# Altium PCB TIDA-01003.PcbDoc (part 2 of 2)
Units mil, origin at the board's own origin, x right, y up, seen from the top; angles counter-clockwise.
Board outline 1055.12 x 1877.5 mil, 6 copper layers (Layer 1 - Top Layer, Layer 2 - GND, Layer 3 - Signal, Layer 4 - Power, Layer 5 - GND, Layer 6 - Bottom Layer), stack 66.271 mil thick; 84 components, 50 nets, 343 pads, 124 vias.
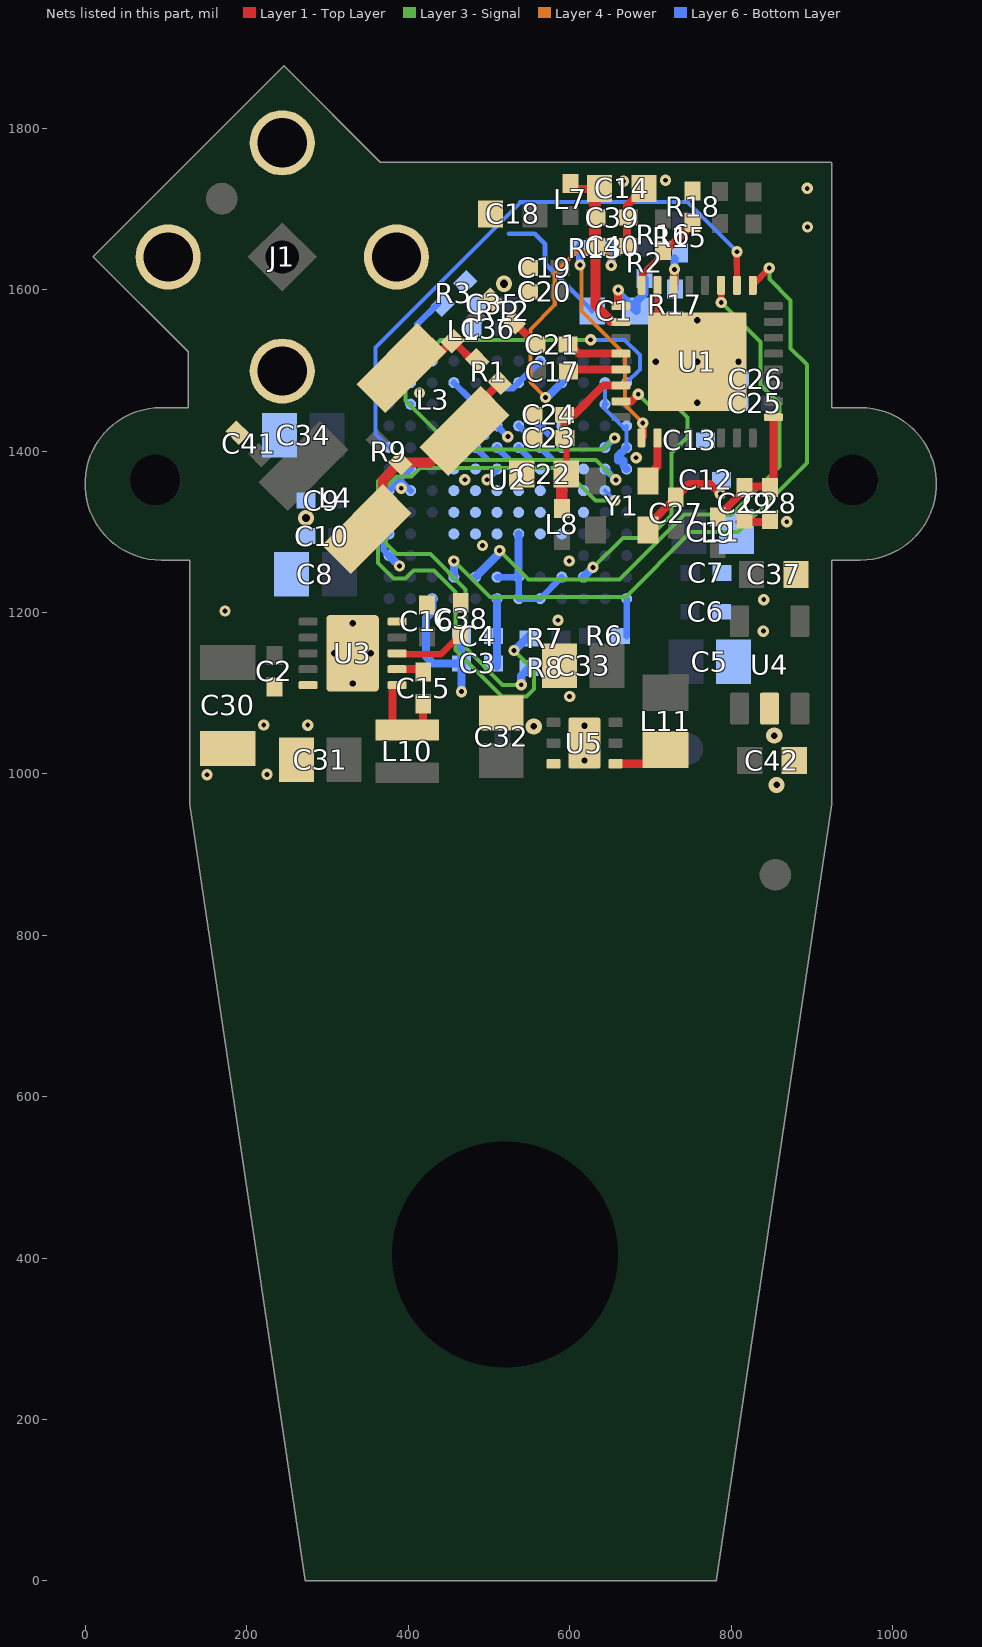
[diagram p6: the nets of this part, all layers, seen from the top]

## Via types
v1: diameter 14, hole 6, Layer 1 - Top Layer to Layer 6 - Bottom Layer, tented both sides, 103 vias
v2: diameter 19.68, hole 7.87, Layer 1 - Top Layer to Layer 6 - Bottom Layer, 10 vias
v3: diameter 20, hole 8, Layer 1 - Top Layer to Layer 6 - Bottom Layer, tented both sides, 6 vias
v4: diameter 20, hole 10, Layer 1 - Top Layer to Layer 6 - Bottom Layer, tented both sides, 4 vias
v5: diameter 19.68, hole 7.87, Layer 1 - Top Layer to Layer 6 - Bottom Layer, tented bottom, 1 vias

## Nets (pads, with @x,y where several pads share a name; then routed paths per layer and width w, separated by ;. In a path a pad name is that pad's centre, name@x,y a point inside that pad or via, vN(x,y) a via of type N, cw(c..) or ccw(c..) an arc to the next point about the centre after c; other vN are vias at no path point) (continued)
GND: C1.2 C2.2 C3.2 C4.2 C5.2 C6.2 C7.2 C8.2 C9.2 C10.2 C11.2 C12.2 C13.2 C14.2 C16.2 C18.2 C19.2 C20.2 C22.2 C23.2 C24.2 C25.2 C26.2 C27.2 C28.2 C29.2 C30.2 C31.2 C32.2 C33.2 C34.2 C35.2 C36.2 C37.2 C38.2 C39.2 C40.2 C41.2 C42.2 J1.2 J1.3 J1.4 J1.5 R3.1 R12.2 R17.1 R18.1 U1.7 U1.33 U2.A3 U2.A7 U2.A8 U2.B6 U2.B7 U2.B9 U2.C1 U2.D1 U2.D4 U2.D5 U2.D6 U2.D7 U2.D8 U2.D9 U2.E4 U2.E5 U2.E6 U2.E7 U2.E8 U2.E9 U2.E10 U2.F1 U2.F2 U2.F4 U2.F5 U2.F6 U2.F7 U2.F8 U2.F9 U2.F10 U2.G2 U2.G4 U2.G5 U2.G6 U2.G7 U2.G8 U2.G9 U2.G10 U2.G12 U2.H4 U2.H5 U2.H6 U2.H7 U2.H8 U2.H9 U2.H12 U2.J4 U2.J5 U2.J6 U2.J7 U2.J8 U2.J9 U2.J12 U2.K2 U2.K11 U2.L2 U2.L4 U2.L6 U2.L7 U2.L11 U2.M8 U3.5 U3.10 U3.11@331,1149.5 U4.2 U5.6 U5.7@618.3,1038.3 Y1.2 | length 1460.2
  Layer 1 - Top Layer w8: U1.33@708.95,1560.22 U1.7@708.95,1605.5
  Layer 1 - Top Layer w10: C40.2@671.1,1655.09 671.1,1704.54 C14.2@692.06,1725.5 ; Y1.2@696.98,1307.99 732.68,1343.69 C27.2@733,1343.69 ; C27.2@733,1344.54 747.86,1359.4 774,1359.5 v1(786.5,1347) ; C29.2@810.7,1312.41 C28.2@847.6,1312.41
  Layer 6 - Bottom Layer w5: U2.K11@641.2,1454.8 U2.J12@667.5,1428.5 ; U2.K11@643.6,1461.5 U2.L11@643.63,1479.17 ; U2.H12@670.65,1404.59 U2.J12@670.65,1431.36
  Layer 6 - Bottom Layer w6: 525,1669.5 556.7,1669.3 569.5,1656.5 569.5,1632 C1.2@627.84,1573.9
  Layer 6 - Bottom Layer w8: U2.C1@376.16,1270.73 369.47,1277.42 369.47,1290.81 U2.D1@376.16,1297.5 ; U2.F1@376.16,1351.04 389.54,1364.43 ; U2.F2@402.93,1351.04 389.54,1364.43 ; U2.G2@402.93,1377.82 389.54,1364.43 ; U2.L2@402.93,1484.9 U2.L2@402.93,1484.96 ; U2.H4@456.47,1404.59 469.86,1391.2 ; U2.J4@456.47,1431.36 469.86,1417.97 ; U2.L4@456.47,1484.9 477.36,1464.02 U2.J5@477.36,1432.97 ; U2.H5@483.25,1404.59 496.63,1391.2 ; U2.J5@483.25,1431.36 496.63,1417.97 ; v1@497,1364 U2.G6@509.79,1376.75 ; U2.B6@510.02,1243.96 U2.B7@536.79,1243.96 U2.A7@536.79,1217.19 U2.A8@563.56,1217.19 U2.B9@590.33,1243.96 ; U2.H6@510.02,1404.59 523.4,1391.2 ; U2.J6@510.02,1431.36 v1(523.4,1417.97) ; U2.L6@510.02,1484.9 516.95,1477.97 529.86,1477.97 550.17,1498.29 ; U2.H7@536.79,1404.59 550.17,1391.2 ; U2.J7@536.79,1431.36 550.17,1417.97 ; 550.17,1498.29 U2.M8@563.56,1511.67 ; U2.H8@563.56,1404.59 576.95,1391.2 ; U2.J8@563.56,1431.36 576.95,1417.97
  Layer 6 - Bottom Layer w10: U2.C1@376.16,1270.73 v1(389.1,1257.8) ; U2.A3@429.7,1217.19 429.7,1200.74 422,1193.04 422,1145.5 430.6,1136.9 C3.2@466.11,1136.9 ; v1(466,1102) 466.11,1122.39 C3.2@466.11,1136.9 ; C4.2@466.11,1170.7 C3.2@466.11,1136.9 ; U2.B7@536.79,1243.96 U2.D7@536.79,1297.5 ; 660.1,1388.36 660.1,1394.04 U2.H12@670.65,1404.59 ; 666.5,1388.36 666.5,1381.96 U2.G12@670.65,1377.82 ; R17.1@730.97,1562.18 v5(758,1562.18) v5@757.33,1561.51 ; C25.2@809.81,1459.45 v2@809.81,1510.37
  Layer 6 - Bottom Layer w15: J1.2@363.97,1627.31 J1.2@381.3,1644.63
  other v1: 150.5,999 225,999.5 275.5,1060.5 221,1060.8 600,1096 840,1177 585.5,1190.5 173,1202 840.5,1216 599.4,1264 492,1283.2 869,1312.5 391.3,1354 470.1,1364.5 497.5,1364.5 682.4,1391.8 414,1472 894.7,1677.9 894.4,1725.7 666.8,1734.5 718.7,1735.8
  other v2: 618.3,1016.65 618.3,1059.95 331,1112.1 308.36,1149.5 353.64,1149.5 331,1186.9 758,1459.82 706.82,1511 758,1511 809.18,1511
  other v3: 856.5,986.5 853.5,1047.5 555.5,1059
  other v4: 273.5,1317 518.5,1607.5
HSYNC: U1.1 U2.B4 | length 834.4
  Layer 1 - Top Layer w8: U1.1@827.06,1605.5 828.16,1606.6 v1(847.4,1627)
  Layer 3 - Signal w5: v1(456.5,1263.8) 501,1219.5 669.5,1219.5 750,1300 808,1300 ; 808.5,1300 894,1385.5 894,1507.1 873.7,1527.4 873.7,1586.8 847.4,1613.1 v1(847.4,1627) v1@847.4,1626.9
  Layer 6 - Bottom Layer w10: U2.B4@456.47,1243.96 v1(456.5,1263.8)
NetC1_1: C1.1 R2.1 U1.9 | length 95.5
  Layer 1 - Top Layer w10: U1.9@660.2,1583.21 v1(660.2,1599.6)
  Layer 6 - Bottom Layer w10: v1(660.2,1599.6) 660.2,1596.66 C1.1@682.96,1573.9 682.96,1585.26 692.8,1595.1 R2.1@692.8,1613.82
NetC3_1: C3.1 C4.1 U2.A6 | length 84.6
  Layer 6 - Bottom Layer w10: U2.A6@508.6,1217.19 U2.A6@508.6,1218.13 ; C3.1@510,1133.5 U2.A6@510.02,1217.19
NetC14_1: C14.1 C39.1 C40.1 L7.2 U1.10 | length 209.4
  Layer 1 - Top Layer w10: L7.2@597.19,1725 C14.1@636.44,1725
  Layer 1 - Top Layer w12: 631.9,1580.3 651.2,1561 ; 631.9,1582.5 C40.1@631.9,1650.9
  Layer 1 - Top Layer w15: C40.1@631.29,1652.41 631.6,1673.41 C14.1@631.4,1726.9
NetC15_1: C15.1 U3.2 | length 28.4
  Layer 1 - Top Layer w10: U3.2@382.62,1129.81 C15.1@411,1130
NetC15_2: C15.2 L10.1 U3.1 | length 90.4
  Layer 1 - Top Layer w10: L10.1@380.5,1054.5 U3.1@380.62,1110.13 ; L10.1@418.5,1049.5 C15.2@418.5,1084.31
NetC17_2: C17.2 U1.13 | length 62.7
  Layer 1 - Top Layer w10: C17.2@601,1501.17 U1.13@663.67,1501.17
NetC21_1: C21.1 R12.1 | length 22.9
  Layer 1 - Top Layer w10: R12.1@537.19,1553.5 C21.1@553.5,1537.5
NetC21_2: C21.2 U1.12 | length 71.4
  Layer 1 - Top Layer w10: C21.2@597.69,1534 610.83,1520.85 U1.12@663.67,1520.85
NetC22_1: C22.1 C23.1 C24.1 L8.2 U1.14 | length 194
  Layer 1 - Top Layer w8: C22.1@596.06,1374.5 C23.1@596.06,1409.41
  Layer 1 - Top Layer w10: C23.1@593.68,1417.2 C24.1@593.68,1445 605.31,1445.01 641.7,1481.4 U1.14@663.67,1481.49
  Layer 1 - Top Layer w14: L8.2@590.2,1327.39 C22.1@590.2,1373.64
NetC28_1: C28.1 C29.1 L9.2 U1.25 | length 163.5
  Layer 1 - Top Layer w10: L9.2@783.5,1318.69 C29.1@812,1347.19 ; C29.1@812,1356 816.48,1356.02 846.8,1356.18 852.65,1362.03 U1.25@852.65,1442.11
NetC38_1: C38.1 U3.3 | length 88.5
  Layer 1 - Top Layer w8: U3.3@386.5,1148.5 440.5,1148.5 C38.1@465,1172.82
NetL1_2: L1.2 L3.1 R1.2 | length 70.8
  Layer 1 - Top Layer w10: L3.1@430.5,1513 L1.2@455,1537.5 ; L1.2@457,1535 R1.2@482.58,1509.42
NetL3_2: L3.2 L4.1 R1.1 R9.2 | length 183.4
  Layer 1 - Top Layer w10: L3.2@465.39,1423.89 L3.2@470.61,1423.89 ; L3.2@488,1459.5 R1.1@512.5,1484
  Layer 1 - Top Layer w12: L4.1@368.5,1342.5 368.5,1364.5 390,1386 427.5,1386 L3.2@465.39,1423.89
NetL11_1: L11.1 U5.1 | length 45
  Layer 1 - Top Layer w10: U5.1@656.69,1012.71 L11.1@701.64,1012.71
NetR3_2: R3.2 U2.M3 | length 89.7
  Layer 6 - Bottom Layer w8: U2.M3@429.7,1511.67 411.22,1530.15 411.22,1557.13 R3.2@437.1,1583
NetR6_1: R6.1 U2.A12 | length 46.3
  Layer 6 - Bottom Layer w8: R6.1@670.6,1170.9 U2.A12@670.65,1217.19
NetR7_1: R7.1 U2.G11 | length 836.4
  Layer 3 - Signal w5: 396.6,1378.5 377.6,1378.5 362.4,1363.3 362.4,1261.4 381.7,1242.1 396.4,1242.1 406.2,1251.9 432.1,1251.9 458.5,1225.5 458.5,1153.5 516,1096 546.5,1096 556,1105.5 556,1128 v1(531,1153) ; 397.2,1378.5 407.7,1389 632.7,1389 v1(657.26,1364.43)
  Layer 6 - Bottom Layer w8: U2.G11@643.88,1377.82 v1(657.26,1364.43)
  Layer 6 - Bottom Layer w10: v1(531,1153) 531.82,1153 R7.1@549.82,1171
NetR8_1: R8.1 U2.F11 | length 704.8
  Layer 3 - Signal w5: v1(540,1110.5) 517,1110.5 471,1156.5 471,1228.5 427.4,1272.3 385.6,1272.3 372.5,1285.4 372.5,1355.8 385.2,1368.5 404.2,1368.5 414.7,1379 591.7,1379 631.8,1338.9 v1(656.12,1338.87)
  Layer 6 - Bottom Layer w5: U2.F11@643.88,1351.04 v1(656.12,1338.87)
  Layer 6 - Bottom Layer w10: v1(540,1110.5) 540,1121.68 R8.1@549.82,1131.5
NetR13_1: R13.1 U1.17 | length 268.9
  Layer 1 - Top Layer w10: U1.17@690.6,1418.01 v1(690.6,1434.9)
  Layer 4 - Power w5: v1(612.7,1630.8) 614.5,1629 614.5,1573.54 668.4,1519.7 668.4,1457.1 v1(690.6,1434.9)
  Layer 6 - Bottom Layer w10: v1(612.7,1630.8) R13.1@612.7,1654.59
NetR15_1: R15.1 R17.2 U1.6 | length 56.1
  Layer 1 - Top Layer w10: U1.6@730,1607.02 v1(730,1625.3)
  Layer 6 - Bottom Layer w10: R17.2@730,1601.19 v1(730,1625.3) R15.1@730,1639.01
NetR16_1: R16.1 R18.2 U1.8 | length 97.3
  Layer 1 - Top Layer w8: U1.8@690.16,1606.01 690.16,1619.01 R16.1@712.16,1641.01
  Layer 1 - Top Layer w10: R16.1@715.8,1645.01 752.3,1681.51 R18.2@752.3,1683.11
NetU1_18: U1.18 Y1.3 | length 52.5
  Layer 1 - Top Layer w10: Y1.3@696.98,1369.01 708.94,1380.98 U1.18@708.94,1416.52
NetU2_H11: U2.H11 U2.L12 | length 696.4
  Layer 3 - Signal w5: v1(626,1538) 440,1538 396.5,1494.8 396.5,1462.5 457,1402 641.5,1402.2 v1(655.7,1416.4)
  Layer 6 - Bottom Layer w5: v1(626,1538) 668.21,1538 687.13,1519.07 687.1,1501.4 U2.L12@670.65,1484.9
  Layer 6 - Bottom Layer w8: U2.H11@643.88,1404.59 v1(655.7,1416.4)
NRST: U1.15 U2.B10 | length 367.8
  Layer 1 - Top Layer w10: U1.15@663.67,1461.8 676.3,1461.8 v1@685,1470.5
  Layer 3 - Signal w5: v1(629,1256) 665.9,1292.4 697.68,1292.4 725.9,1320.62 725.9,1397.6 745.9,1417.6 745.9,1441.9 731.4,1456.4 699.1,1456.4 v1(684.9,1470.6)
  Layer 6 - Bottom Layer w10: U2.B10@617.1,1243.96 v1(629,1256)
PCLK: U1.3 U2.B5 | length 719
  Layer 1 - Top Layer w8: v1@787.69,1584.59 U1.3@787.69,1605.5
  Layer 3 - Signal w5: v1(513.2,1276.9) 549,1241 661.5,1241 742,1321.5 800.5,1321.5 860,1381 859.9,1458.9 836.7,1482.1 836.7,1535.4 v1(787.9,1584.2)
  Layer 6 - Bottom Layer w10: U2.B5@483.25,1243.96 513.2,1273.91 v1(513.2,1276.9)
VSYNC: U1.2 U2.H1 | length 719.9
  Layer 1 - Top Layer w8: v1(807.3,1647.2) U1.2@807.37,1605.5
  Layer 6 - Bottom Layer w5: U2.H1@376.16,1404.59 359.3,1421.4 359.5,1528.5 538.5,1707.5 ; 538.5,1708.5 746,1708.5 v1(807.3,1647.2)
XCLK: R13.2 U2.L9 | length 318.1
  Layer 4 - Power w5: v1(570,1466.5) 551.5,1485 551.5,1551 581.5,1581 581.5,1620.5 607.6,1646.6 644.7,1646.64 651.6,1639.74 v1(651.6,1630.1)
  Layer 6 - Bottom Layer w10: v1(570,1466.5) 571.93,1466.5 U2.L9@590.33,1484.9 ; v1(651.6,1630.1) R13.2@651.6,1652.71
pads on no net: FID1.1 FID2.1 FID3.1 FID4.1 LBL1.0 U2.A1 U2.A2 U2.A4 U2.A5 U2.A9 U2.A10 U2.A11 U2.B1 U2.B2 U2.B11 U2.B12 U2.C2 U2.C11 U2.F12 U2.G1 U2.J1 U2.J11 U2.K1 U2.L1 U2.L5 U2.M1 U2.M2 U2.M11 U2.M12 U3.11@321.16,1089.26 U3.11@321.16,1209.74 U3.11@331,1124.7 U3.11@331,1174.3 U3.11@340.84,1089.26 U3.11@340.84,1209.74 U4.4 U5.7@618.3,1020.58 U5.7@618.3,1056.02

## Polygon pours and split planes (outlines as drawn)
GND on Layer 6 - Bottom Layer "LAYER_6_-_BOTTOM_LAYER_GND_P074" (solid, remove dead copper, pour order 74): 755.19,1435 755.19,1109.23 890,1109.23 890,1315 770,1435
GND on Layer 6 - Bottom Layer "LAYER_6_-_BOTTOM_LAYER_GND_P072" (solid, remove dead copper, pour order 72): 231.6,1337.3 231.6,1212 294.8,1212 294.8,1372.3 266.6,1372.3
2V8 on Layer 6 - Bottom Layer "LAYER_6_-_BOTTOM_LAYER_2V8_P066" (solid, remove dead copper, pour order 66): 650.2,1473.4 650.2,1333.2 712,1271.4 712,1110.5 769.09,1110.5 769.09,1364.91 741,1393 741,1432 693,1480 656.8,1480
2V8 on Layer 6 - Bottom Layer "LAYER_6_-_BOTTOM_LAYER_2V8_P064" (solid, remove dead copper, pour order 64): 593.5,1346.3 593.5,1255 671.1,1255 671.1,1346.3
GND on Layer 6 - Bottom Layer "LAYER_6_-_BOTTOM_LAYER_GND_P046" (solid, remove dead copper, pour order 46): 137.5,1488.3 137.5,1392 295,1392 295,1535.8 263.9,1566.9 216.1,1566.9
1V8 on Layer 6 - Bottom Layer "LAYER_6_-_BOTTOM_LAYER_1V8_P044" (solid, remove dead copper, pour order 44): 292.8,1391.5 292.8,1212.1 454,1212.1 454,1466.5 367.8,1466.5
GND on Layer 6 - Bottom Layer "LAYER_6_-_BOTTOM_LAYER_GND_P084" (solid, remove dead copper, pour order 84): 451.18,1394.31 451.18,1294.3 464.6,1294.3 483.2,1275.7 500.12,1275.7 500.12,1284.42 510,1294.3 620.1,1294.3 620.1,1430.39 562.99,1487.5 451.18,1487.5
GND on Layer 6 - Bottom Layer "LAYER_6_-_BOTTOM_LAYER_GND_P088" (solid, remove dead copper, pour order 88): 456.6,1676 456.6,1567.71 481.32,1542.99 527.5,1542.99 527.5,1676
GND on Layer 1 - Top Layer "LAYER_1_-_TOP_LAYER_GND_P078" (solid, remove dead copper, pour order 78): 171,1493.5 171,1424.5 221.5,1374 289,1441.5 289,1524.5 269,1544.5 222,1544.5
2V8 on Layer 1 - Top Layer "LAYER_1_-_TOP_LAYER_2V8_P062" (solid, remove dead copper, pour order 62): 606.9,1283.2 673.6,1216.5 777,1113.1 830.55,1113.1 830.55,1346 733,1346 733,1325.5 673.6,1325.5 673.6,1346 673.6,1438.6 606.9,1438.6
GND on Layer 1 - Top Layer "LAYER_1_-_TOP_LAYER_GND_P060" (solid, remove dead copper, pour order 60): 830.55,1267.01 830.55,966.05 897.2,966.05 897.19,1296.8 865.34,1328.66 830.55,1328.66
3V3 on Layer 1 - Top Layer "LAYER_1_-_TOP_LAYER_3V3_P058" (solid, remove dead copper, pour order 58): 796.5,1109.51 796.5,967.55 830.5,967.55 830.5,1109.51
GND on Layer 1 - Top Layer "LAYER_1_-_TOP_LAYER_GND_P052" (solid, remove dead copper, pour order 52): 141.1,976.5 287,976.5 287,1068 301.45,1082.45 342.56,1082.45 360.91,1100.81 360.91,1173.5 370.71,1183.29 394.5,1183.29 394.5,1195 403.7,1204.2 471.5,1204.2 471.5,1230 336.61,1230 284,1282.61 284,1329 278,1335 256,1335 256,1183.29 292.9,1183.29 292.9,1108.71 201.71,1108.71 141.1,1108.71
"9V IN" on Layer 1 - Top Layer "LAYER_1_-_TOP_LAYER_9V_IN_P048" (solid, remove dead copper, pour order 48): 199.87,1395.87 215.5,1380.25 215.5,1361 250.5,1326 326,1401.5 291,1436.5 241.75,1387.25 216.5,1412.5
1V8 on Layer 1 - Top Layer "LAYER_1_-_TOP_LAYER_1V8_P040" (solid, remove dead copper, pour order 40): 543.8,1208.2 543.8,1086.3 564.3,1065.8 564.3,1051.3 588.3,1051.3 595,1058 747.5,1058 747.5,1109.5 670.35,1186.65 670.35,1212.85 603.5,1276.1 603.5,1350.3 456.3,1350.3 456.3,1374.5 430,1374.5 409.9,1354.4 409.9,1307.7 409.9,1254.1 438,1226 526,1226
3V3 on Layer 1 - Top Layer "LAYER_1_-_TOP_LAYER_3V3_P038" (solid, remove dead copper, pour order 38): 293.5,970.5 497.5,970.5 497.5,1024.5 369.83,1024.5 343.33,1051 293.5,1051
GND on Layer 1 - Top Layer "LAYER_1_-_TOP_LAYER_GND_P036" (solid, remove dead copper, pour order 36): 458.5,1221 458.5,1048.5 564.3,1048.5 564.3,1077.8 573.8,1087.3 584.8,1087.3 597.6,1074.5 597.6,1022.6 588.8,1013.8 570.3,1013.8 570.3,1001.3 637.8,1001.3 637.8,1062.8 610.6,1090 610.6,1178.4 610.6,1180.9 589.5,1202 542.5,1202 523.5,1221
3V3 on Layer 1 - Top Layer "LAYER_1_-_TOP_LAYER_3V3_P034" (solid, remove dead copper, pour order 34): 477.8,1045 477.8,970.5 565.3,970.5 565.3,1019.8 575.8,1030.3 593.3,1030.3 593.3,1045
GND on Layer 1 - Top Layer "LAYER_1_-_TOP_LAYER_GND_P008" (solid, pour order 8): 537,1729 537,1662.5 560.5,1639 560.5,1592.11 528.11,1592.11 514.41,1578.41 361.34,1578.41 319,1620.75 319,1669.7 394.3,1745 521,1745
GND on Layer 1 - Top Layer "LAYER_1_-_TOP_LAYER_GND_P010" (solid, pour order 10): 567,1457.4 567,1352.8 460,1352.8 460,1457.4
GND on Layer 1 - Top Layer "LAYER_1_-_TOP_LAYER_GND_P090" (solid, remove dead copper, pour order 90): 658.1,1751.6 658.31,1644.3 694.3,1644.3 694.3,1708.1 762.3,1708.1 762.3,1751.6 694.3,1751.6
"9V IN" on Layer 1 - Top Layer "LAYER_1_-_TOP_LAYER_9V_IN_P092" (solid, remove dead copper, pour order 92): 141.12,1232.12 141.12,1215.5 141.12,1112.12 261.12,1112.12 261.12,1141.5 292.9,1141.5 292.9,1176.5 251.5,1176.5 251.5,1396 200,1396 200,1317 141.12,1258.12
1V8 on Layer 1 - Top Layer "LAYER_1_-_TOP_LAYER_1V8_P094" (solid, remove dead copper, pour order 94): 619,1711.04 541.5,1710.89 541.5,1654.03 575.5,1654.03 575.5,1587.5 588.08,1574.92 619,1574.92 619,1654.03
GND on Layer 2 - GND "LAYER_2_-_GND_GND_P028" (solid, remove dead copper, pour order 28): -5,1880 -5,962.5 1060,962.5 1060,1751 361.5,1751 232.5,1880
GND on Layer 5 - GND "LAYER_5_-_GND_GND_P030" (solid, remove dead copper, pour order 30): -5,1880 -5,962.5 1060,962.5 1060,1880 0,1880
3V3 on Layer 4 - Power "LAYER_4_-_POWER_3V3_P054" (solid, remove dead copper, pour order 54): 138.5,1161.5 138.5,962.5 914.5,962.5 914.5,1069.5 282.5,1069.5 221.5,1130.5 190.5,1161.5
1V8 on Layer 4 - Power "LAYER_4_-_POWER_1V8_P056" (solid, remove dead copper, pour order 56): 140.9,1748.1 140.9,1061.6 681.63,1061.6 681.63,1103.8 681.63,1175.6 656.1,1175.6 582.9,1248.8 582.9,1528.5 843,1528.5 843,1748.1
2V8 on Layer 4 - Power "LAYER_4_-_POWER_2V8_P068" (solid, remove dead copper, pour order 68): 544.09,1641 544.23,1299.32 660.91,1182.7 686.1,1182.7 686.1,1070.4 915.37,1070.4 915.79,1747.6 845.9,1747.6 845.9,1641

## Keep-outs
Keep-Out Layer:
  lines w10: 5.93,1637.45 cw(c9.45,1641) 5.92,1644.54 5.93,1644.55 ; 5.93,1637.45 122.32,1521.06 122.32,1458.99 93.88,1458.99 ; 5.93,1637.45 5.92,1637.46 cw(c9.45,1641) 5.93,1644.55 ; 5.93,1644.55 242.4,1881.02 ; 93.83,1458.99 cw(c93.88,1359.5) 93.88,1458.99 ; 93.83,1458.99 ccw(c93.88,1359.5) 93.88,1260.01 ; 93.83,1458.99 cw(c93.88,1453.99) 93.88,1458.99 ; 93.83,1458.99 cw(c93.88,1453.99) 93.88,1458.99 ; 93.88,1260.01 93.88,1260.01 ; 93.88,1260.01 124.31,1260.01 124.31,962.59 ; 93.88,1458.99 ccw(c93.88,1453.99) 93.88,1458.99 ; 124.31,961.86 ccw(c129.31,961.86) 124.31,961.86 ; 124.31,961.86 ccw(c129.31,961.86) 124.6,960.19 ; 124.31,961.86 ccw(c129.31,961.86) 124.6,960.19 ; 124.31,961.86 124.31,962.49 ; 124.31,961.86 124.31,962.41 ; 124.31,962.41 cw(c129.31,962.5) 124.31,962.49 ; 124.31,962.41 124.31,962.59 ; 124.31,962.49 cw(c129.31,962.5) 124.31,962.59 ; 124.31,962.49 cw(c129.31,962.5) 124.31,962.59 ; 124.6,960.19 267.26,-0.73 ; 242.4,1881.02 cw(c245.95,1877.5) 249.49,1881.04 249.5,1881.02 ; 242.4,1881.02 242.42,1881.04 cw(c245.95,1877.5) 249.5,1881.02 ; 249.5,1881.02 367.39,1763.13 923.6,1763.13 ; 267.26,-0.73 ccw(c272.2,0) 272.2,-5 ; 267.26,-0.73 ccw(c272.2,0) 272.2,-5 ; 272.2,-5 781.7,-5 ; 781.7,-5 ccw(c781.7,0) 786.65,-0.73 ; 781.7,-5 ccw(c781.7,0) 786.65,-0.73 ; 786.65,-0.73 929.3,960.19 ; 923.6,1763.13 cw(c923.6,1758.13) 927.13,1761.67 ; 923.6,1763.13 cw(c923.6,1758.13) 927.15,1761.65 ; 927.15,1761.65 928.11,1760.69 ; 927.13,1761.67 927.15,1761.65 ; 928.11,1760.69 cw(c924.59,1757.14) 929.59,1757.14 ; 928.11,1760.69 928.13,1760.67 cw(c924.59,1757.14) 929.59,1757.14 ; 929.3,960.19 ccw(c924.59,961.86) 929.59,961.86 ; 929.3,960.19 ccw(c924.59,961.86) 929.59,961.86 ; 929.59,961.86 ccw(c924.59,961.86) 929.59,961.86 ; 929.59,961.86 929.59,962.43 ; 929.59,961.86 929.59,962.5 ; 929.59,962.43 ccw(c924.59,962.5) 929.59,962.5 ; 929.59,962.43 929.59,962.57 ; 929.59,962.5 ccw(c924.59,962.5) 929.59,962.57 ; 929.59,962.5 ccw(c924.59,962.5) 929.59,962.57 ; 929.59,962.5 ccw(c924.59,962.5) 929.59,962.5 ; 929.59,962.5 ccw(c924.59,962.5) 929.59,962.5 ; 929.59,962.57 929.59,1260.01 960.02,1260.01 ccw(c960.02,1359.5) 1059.51,1359.5 ccw(c960.02,1359.5) 960.07,1458.99 ; 929.59,1757.14 929.59,1458.99 960.02,1458.99 ; 960.02,1458.99 cw(c960.02,1359.5) 960.07,1458.99 ; 960.02,1458.99 cw(c960.02,1453.99) 960.07,1458.99 ; 960.02,1458.99 cw(c960.02,1453.99) 960.07,1458.99
  text ".Layer_Name" at 577,-858.49 h60

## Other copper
Layer 1 - Top Layer:
  text ".Layer_Name" at 577,-858.49 h60
Layer 2 - GND:
  text ".Layer_Name" at 582,-853 h60
Layer 3 - Signal:
  text ".Layer_Name" at 577,-858.49 h60
Layer 4 - Power:
  text ".Layer_Name" at 577,-858.49 h60
Layer 5 - GND:
  text ".Layer_Name" at 608,-850 h60
Layer 6 - Bottom Layer:
  region net GND: 664.6,1376.7 681,1376.7 690.5,1386.2 690.5,1397.1 680.8,1406.8 667.12,1406.8 655.1,1394.78 655.1,1386.2
  region net 2V8: 624.2,1432.7 612.33,1432.7 612.33,1402.6 621.67,1402.6 633.7,1414.62 633.7,1423.2
  region net GND: 375.4,1344.3 401.7,1344.3 409.7,1352.3 409.7,1377.8 407.2,1380.3 396.6,1380.3 371.7,1355.4 371.7,1348
  region net GND: 397.2,1455.7 409.5,1455.7 412.3,1458.5 412.3,1488.6 409.2,1491.7 397.5,1491.7 394.36,1488.56 394.36,1458.54
  text ".Layer_Name" at 577,-858.49 h60

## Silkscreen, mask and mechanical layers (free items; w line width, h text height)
Top Overlay:
  text ".Layer_Name" at 577,-858.49 h40
Bottom Overlay:
  text "TIDA-01003" at 636.5,876.5 h40
  text ".Layer_Name" at 577,-858.49 h60
Top Paste:
  text ".Layer_Name" at 577,-858.49 h60
Bottom Paste:
  text ".Layer_Name" at 577,-858.49 h60
Top Solder:
  text ".Layer_Name" at 577,-858.49 h60
Bottom Solder:
  text ".Layer_Name" at 577,-858.49 h60
Drill Guide:
  text ".Layer_Name" at 577,-858.49 h60
M1 Board Outline:
  lines w10: 129.31,961.86 129.31,1265.01 93.88,1265.01 cw(c93.88,1359.5) 93.88,1453.99 127.32,1453.99 127.32,1523.13 9.45,1641 245.95,1877.5 365.32,1758.13 923.6,1758.13 ; 129.31,962.5 272.2,0 781.7,0 924.59,962.5 ; 133.99,937.5 160.94,937.5 ; 192.94,937.5 224.57,937.5 ; 256.57,937.5 288.21,937.5 ; 320.21,937.5 351.85,937.5 ; 383.85,937.5 415.49,937.5 ; 447.49,937.5 479.12,937.5 ; 511.12,937.5 542.76,937.5 ; 516.94,898.5 533.94,898.5 ; 526.94,850.5 526.94,890.5 ; 574.76,937.5 606.4,937.5 ; 638.4,937.5 670.04,937.5 ; 702.04,937.5 733.68,937.5 ; 765.68,937.5 797.31,937.5 ; 829.31,937.5 860.95,937.5 ; 892.95,937.5 919.95,937.5 ; 924.59,961.86 924.59,1265.01 960.02,1265.01 ccw(c960.02,1359.5) 960.02,1453.99 924.59,1453.99 924.59,1757.14 ; 506.94,890.5 546.94,890.5 526.94,910.5 506.94,890.5
  text "V-SCORE" at 366.94,781.5 h75
  text ".Layer_Name" at 577,-858.49 h60
M2 Board Dimensions:
  rectangle: 0,-275 125,-150
  rectangle: 125,-400 500,-275
  lines w7: 0,-275 1000,-275 ; 125,-400 125,-150 ; 250,-400 250,-150 ; 500,-400 500,-150 ; 750,-400 750,-150 ; 0,-400 1000,-400 1000,-150 0,-150 0,-400
  text ".Layer_Name" at 577,-858.49 h60
M3 3D STEP Top:
  text ".Layer_Name" at 577,-858.49 h60
M4 3D STEP Bottom:
  text ".Layer_Name" at 577,-858.49 h60
M5 Assembly Top:
  lines w10: -292,-930.17 6308,-930.17 ; -292,-726.83 6310,-726.83 ; -292,-523.5 -292,-1133.5 3713,-1133.5 6310,-1133.5 6310,-523.5 -291.5,-523.5 -291.5,-1133.5 1284,-1133.5 ; 2173,-1133.5 2173,-523.5 ; 3440,-726.83 3440,-523.5 ; 4280,-726.83 4280,-523.5 ; 4902,-1140 4902,-937.17
  text "COMPONENTS MARKED 'DNP' SHOULD NOT BE POPULATED." at 1153.5,-318.5 h60
  text "ASSEMBLY VARIANT:" at 1153,-434 h60
  text ".VariantName" at 2189,-434 h60
  text "PCB VIEWED FROM TOP SIDE" at -228.5,-655.67 h60
  text "BOARD #:" at 2248,-655.67 h60
  text ".PRJ_Number" at 2793.5,-655.67 h60
  text "REV:" at 3638,-655.67 h60
  text ".PCB_Rev" at 3929.5,-655.67 h60
  text "SVN REV:" at 4476,-655.67 h60
  text ".VersionControl_RevNumber" at 4982,-655.67 h60
  text "TID #:" at 2248,-859 h60
  text ".TID" at 2793.5,-859 h60
  text "PLOT NAME =" at -228.5,-1064.34 h60
  text ".plot_File_Name" at 577,-1064.34 h60
  text "GENERATED    :" at 2250,-1064.34 h60
  text ".Print_Date" at 3119.5,-1064.34 h60
  text ".Print_Time" at 3848.5,-1064.34 h60
  text "TEXAS INSTRUMENTS" at 5113,-1064.34 h60
M6 Assembly Bottom:
  lines w10: -292.5,-727.33 6309.5,-727.33 ; -290.5,-930.67 6309.5,-930.67 ; 1115.5,-1140.5 1115.5,-937.67 ; 1737.5,-727.33 1737.5,-524 ; 2577.5,-727.33 2577.5,-524 ; 3844.5,-1134 3844.5,-524 ; 4733.5,-1134 6309,-1134 6309,-524 -292.5,-524 -292.5,-1134 2304.5,-1134 6309.5,-1134 6309.5,-524
  text "COMPONENTS MARKED 'DNP' SHOULD NOT BE POPULATED." at 6102,-318 h60
  text ".VariantName" at 5058,-434 h60
  text "ASSEMBLY VARIANT:" at 6097,-434 h60
  text ".VersionControl_RevNumber" at 1035.5,-656.17 h60
  text "SVN REV:" at 1541.5,-656.17 h60
  text ".PCB_Rev" at 2088,-656.17 h60
  text "REV:" at 2379.5,-656.17 h60
  text ".PRJ_Number" at 3224,-656.17 h60
  text "BOARD #:" at 3769.5,-656.17 h60
  text "PCB VIEWED FROM BOTTOM SIDE" at 6246,-656.17 h60
  text ".TID" at 3224,-859.5 h60
  text "TID #:" at 3769.5,-859.5 h60
  text "TEXAS INSTRUMENTS" at 904.5,-1064.84 h60
  text ".Print_Time" at 2169,-1064.84 h60
  text ".Print_Date" at 2898,-1064.84 h60
  text "GENERATED    :" at 3767.5,-1064.84 h60
  text ".plot_File_Name" at 5440.5,-1064.84 h60
  text "PLOT NAME =" at 6246,-1064.84 h60
M9 Title Sheet:
  drawing of 57 lines, arcs and shapes, not listed
  text "1" at 739.84,8036.5 h70
  text "2" at 3235.5,8036.5 h70
  text "3" at 5724.84,8036.5 h70
  text "4" at 8231.51,8036.5 h70
  text "5" at 10730.5,8036.5 h70
  text "6" at 13235.5,8036.5 h70
  text "A" at -416.5,6893.5 h70
  text "A" at 14383.5,6893.5 h70
  text "B" at -416.5,4513.5 h70
  text "B" at 14383.5,4513.5 h70
  text "C" at -416.5,2138.5 h70
  text "C" at 14383.5,2138.5 h70
  text "PROJECT TITLE:" at 11343.5,277.5 h45
  text ".PRJ_Title" at 11393.5,144.17 h70
  text "DESIGNED FOR:" at 11343.5,-23.5 h45
  text ".PRJ_Customer" at 11393.5,-163.5 h70
  text "D" at -416.5,-231.5 h70
  text "D" at 14383.5,-231.5 h70
  text "FILE NAME:" at 11343.5,-323.5 h45
  text ".PCB_File_Name_No_Path" at 11393.5,-443.5 h70
  text "Texas Instruments (TI) and/or its licensors do not warrant the accuracy or completeness of this specification" at 6374,-605.34 h45
  text "ENGINEER:" at 11343.5,-613.5 h45
  text "LAYOUT BY:" at 12848.5,-613.5 h45
  text "or any information contained therein. TI and/or its licensors do not warrant that this design will meet" at 6329.01,-718 h45
  text ".PRJ_Engineer" at 11393.5,-768.49 h70
  text ".PCB_Layout" at 12899,-768.49 h70
  text "the specifications, will be suitable for your application or fit for any particular purpose, or will operate in" at 6329.01,-830.67 h45
  text ".Layer_Name" at 577,-858.49 h60
  text "ALTIUM DESIGNER VERSION:" at 12848.5,-923.5 h45
  text "an implementation. TI and/or its licensors do not warrant that the design is production worthy. You should" at 6329.01,-943.33 h45
  text "completely validate and test your design implementation to confirm the system functionality for your application." at 6374,-1056 h45
  text ".print_Scale" at 11393.5,-1056.83 h70
  text ".Application_BuildNumber" at 12899,-1056.83 h70
  text "1" at 739.84,-1263.5 h70
  text "2" at 3235.5,-1263.5 h70
  text "3" at 5724.84,-1263.5 h70
  text "4" at 8231.51,-1263.5 h70
  text "5" at 10730.5,-1263.5 h70
  text "6" at 13235.5,-1263.5 h70
M10 Fab Notes:
  drawing of 173 lines, arcs and shapes, not listed
  text "DESIGN INFORMATION" at 12378.02,6201 h60
  text "MIN. TRACK WIDTH:" at 11733.46,6021 h60
  text "5" at 12829.7,6021 h60
  text "MIL" at 12984.46,6021 h60
  text "MIN. CLEARANCE:" at 11733.46,5889 h60
  text "MIL" at 12984.46,5889 h60
  text "5" at 12827,5887 h60
  text "MIN. VIA PAD SIZE:" at 11733.46,5757 h60
  text "14" at 12799.71,5757 h60
  text "MIL" at 12984.46,5757 h60
  text "0.05mm (2MIL)" at 12428.46,5615.29 h60
  text "MINIMUM ANNULAR RING" at 11404.23,5611 h60
  text "EXTERNAL" at 13136.46,5611 h60
  text "PER" at 11604.23,5493 h60
  text "IPC-D-275 CLASS 2 LEVEL C" at 11824.23,5493 h60
  text "MIL, HOLES" at 13312.46,5380.71 h60
  text "+/-" at 12920,5380 h60
  text "+/-" at 13774,5380 h60
  text "REGISTRATION TOLERANCES:" at 11404.23,5375 h60
  text "METAL" at 12604,5375 h60
  text "5" at 13180.2,5375 h60
  text "3" at 14013.2,5375 h60
  text "MIL" at 14129.46,5375 h60
  text "+/-" at 13774,5262 h60
  text "HOLE SIZE TOLERANCE (UNLESS OTHERWISE SPECIFIED):" at 11404.23,5257 h60
  text "3" at 14013.2,5257 h60
  text "MIL" at 14129.46,5257 h60
  text "TOP layer contains 50 Ohm single-ended trace with 20MIL wide line(J1 to C17)." at 6259.7,5181 h60
  text "MATERIAL:" at 11329.46,5047.54 h60
  text "FR-4 High Tg" at 12315.9,4907.21 h60
  text "FR-408" at 11750.46,4898.64 h60
  text "OTHER" at 13238.46,4898.64 h60
  text "X" at 12161,4895 h60
  text "62 MIL (1.6mm) +/-10%" at 12070.56,4735.92 h60
  text "THICKNESS:" at 11404.23,4731.64 h60
  text "X" at 11942.4,4731.64 h60
  text "OTHER" at 13355.46,4731.64 h60
  text "TOLERANCE:" at 11404.23,4573.64 h60
  text "X" at 12243.53,4573.64 h60
  text "ANSI IPC-6012 TYPE 3 CLASS 2" at 12430.48,4573.64 h60
  text "OTHER +/-" at 12430.46,4417.64 h60
  text "BOW & TWIST:" at 11404.23,4260.64 h60
  text "X" at 12243.53,4260.64 h60
  text "ANSI IPC-6012 TYPE 3 CLASS 2" at 12430.48,4260.64 h60
  text "OTHER +/-" at 12430.46,4102.13 h60
  text "DRILLING:" at 11329.46,3963.64 h60
  text "REFERENCE:" at 11404.23,3846.64 h60
  text "X" at 12052.46,3846.64 h60
  text "AS SHOWN" at 12239.46,3846.64 h60
  text "X" at 12953.46,3846.64 h60
  text "NC_DRILL FILES" at 13090.46,3846.64 h60
  text "PTH COPPER THICKNESS:" at 11404.23,3688.64 h60
  text "X" at 12534.46,3688.64 h60
  text "20-30 um" at 12671.46,3688.64 h60
  text "OTHER" at 13388.46,3688.64 h60
  text "BOARD FINISH:" at 11329.46,3529.64 h60
  text "SILKSCREEN:" at 11484.68,3411.64 h60
  text "X" at 12433.46,3411.64 h60
  text "TOP" at 12559.46,3411.64 h60
  text "X" at 12943.46,3411.64 h60
  text "BOTTOM" at 13070.46,3411.64 h60
  text "SILKSCREEN COLOR:" at 11484.68,3244.64 h60
  text "X" at 12432.42,3244.64 h60
  text "WHITE" at 12559.46,3244.64 h60
  text "OTHER" at 13070.46,3244.64 h60
  text "BLACK" at 13806.46,3091.44 h60
  text "X" at 13157,3086 h60
  text "GREEN" at 12690.46,3085.44 h60
  text "OTHER" at 13308.46,3085.44 h60
  text "SOLDER RESIST COLOR:" at 11484.68,3074.64 h60
  text "X" at 12563.42,2915.44 h60
  text "MATTE" at 12690.46,2915.44 h60
  text "SEMI-GLOSS" at 13308,2914.8 h60
  text "IMMERSION GOLD (ENIG)" at 12390.46,2726.92 h60
  text "ENEPIG" at 13728,2723.64 h60
  text "SURFACE FINISH:" at 11329.46,2722.64 h60
  text "X" at 12203.51,2722.64 h60
  text "IMM. TIN/SILVER OR EQUIV" at 11659,2565.64 h60
  text "OTHER" at 13090.46,2565.64 h60
  text "ARRAY/PANEL:" at 11329.46,2386.64 h60
  text "CUT AND TRIM PER M1 BOARD OUTLINE" at 12390.46,2382.35 h60
  text "N.C. ROUTE" at 12390.46,2230.64 h60
  text "X" at 13069.46,2230.64 h60
  text "V. SCORE" at 13256.46,2230.64 h60
  text "CERTIFICATION:" at 11329.46,2093.64 h60
  text "MATERIALS AND WORKMANSHIP FOR ALL PCBS" at 12054.46,2093.64 h60
  text "TO MEET OR EXCEED THE REQUIREMENTS OF:" at 12054.46,1995.64 h60
  text "X" at 11680.96,1859.13 h60
  text "ANSI IPC-A-600F CLASS ->" at 11819.96,1859.13 h60
  text "X" at 13459.02,1859.13 h60
  text "2" at 13577.96,1859.14 h60
  text "1" at 13262.96,1857.64 h60
  text "3" at 13931.96,1857.64 h60
  text "X" at 12495.02,1699.64 h60
  text "RoHS" at 12631.96,1699.64 h60
  text "OTHER" at 13276.36,1699.64 h60
  text "PER ORDER" at 13673.42,1699.64 h60
  text "ALL BOARDS MUST MEET OR EXCEED UL94-V0 REQUIREMENTS." at 11357,1534 h60
  text "PCB MUST BEAR THE UL94V-0 UL REGISTERED MATERIAL ID NUMBER" at 11357,1414 h60
  text "ADDITIONAL REQUIREMENTS:" at 11329.46,1240.64 h60
  text "MICROSECTION:" at 11404.23,1125.64 h60
  text "YES" at 12309.96,1125.64 h60
  text "REQUIRED" at 13171.46,969.49 h60
  text "BARE BOARD ELEC. TEST:" at 11404.23,966.64 h60
  text "NONE" at 12709.96,966.64 h60
  text "X" at 13044.46,966.64 h60
  text "PER ORDER" at 13763.46,966.64 h60
  text ".Layer_Name" at 577,-858.49 h60
M11 Gerber Information:
  lines w10: -292,-930.17 6308,-930.17 ; -292,-726.83 6310,-726.83 ; -292,-523.5 -292,-1133.5 3713,-1133.5 6310,-1133.5 6310,-523.5 -291.5,-523.5 -291.5,-1133.5 1284,-1133.5 ; 2173,-1133.5 2173,-523.5 ; 3440,-726.83 3440,-523.5 ; 4280,-726.83 4280,-523.5 ; 4902,-1140 4902,-937.17
  text "ALL ARTWORK VIEWED FROM TOP SIDE" at -228.5,-655.67 h60
  text "BOARD #:" at 2248,-655.67 h60
  text ".PRJ_Number" at 2793.5,-655.67 h60
  text "REV:" at 3638,-655.67 h60
  text ".PCB_Rev" at 3929.5,-655.67 h60
  text "SVN REV:" at 4476,-655.67 h60
  text ".VersionControl_RevNumber" at 4982,-655.67 h60
  text "LAYER NAME =" at -228.5,-858.49 h60
  text "TID #:" at 2248,-859 h60
  text ".TID" at 2793.5,-859 h60
  text "PLOT NAME =" at -228.5,-1064.34 h60
  text ".plot_File_Name" at 577,-1064.34 h60
  text "GENERATED    :" at 2250,-1064.34 h60
  text ".Print_Date" at 3119.5,-1064.34 h60
  text ".Print_Time" at 3848.5,-1064.34 h60
  text "TEXAS INSTRUMENTS" at 5113,-1064.34 h60
M12 Stackup:
  drawing of 399 lines, arcs and shapes, not listed
  text "Layer" at 6208.84,7332 h60
  text "Name" at 6618.76,7332 h60
  text "Material" at 8028.34,7332 h60
  text "Thickness" at 8888.11,7332 h60
  text "Constant" at 9537.95,7332 h60
  text "Board Layer Stack" at 10107.81,7332 h60
  text "1" at 6208.84,7212 h60
  text "Top Overlay" at 6618.76,7212 h60
  text "2" at 6208.84,7092 h60
  text "Top Solder" at 6618.76,7092 h60
  text "Solder Resist" at 8028.34,7092 h60
  text "0.40mil" at 8888.11,7092 h60
  text "3.5" at 9537.95,7092 h60
  text "3" at 6208.84,6972 h60
  text "Layer 1 - Top Layer" at 6618.76,6972 h60
  text "Copper" at 8028.34,6972 h60
  text "1.40mil" at 8888.11,6972 h60
  text "4" at 6208.84,6852 h60
  text "Dielectric 1" at 6618.76,6852 h60
  text "370HR" at 8028.34,6852 h60
  text "12.60mil" at 8888.11,6852 h60
  text "4.2" at 9537.95,6852 h60
  text "5" at 6208.84,6732 h60
  text "Layer 2 - GND" at 6618.76,6732 h60
  text "Copper" at 8028.34,6732 h60
  text "1.42mil" at 8888.11,6732 h60
  text "6" at 6208.84,6612 h60
  text "Dielectric 2" at 6618.76,6612 h60
  text "370HR" at 8028.34,6612 h60
  text "8.00mil" at 8888.11,6612 h60
  text "4.2" at 9537.95,6612 h60
  text "7" at 6208.84,6492 h60
  text "Layer 3 - Signal" at 6618.76,6492 h60
  text "Copper" at 8028.34,6492 h60
  text "1.42mil" at 8888.11,6492 h60
  text "8" at 6208.84,6372 h60
  text "Dielectric 3" at 6618.76,6372 h60
  text "370HR" at 8028.34,6372 h60
  text "16.60mil" at 8888.11,6372 h60
  text "4.2" at 9537.95,6372 h60
  text "9" at 6208.84,6252 h60
  text "Layer 4 - Signal2" at 6618.76,6252 h60
  text "Copper" at 8028.34,6252 h60
  text "1.42mil" at 8888.11,6252 h60
  text "10" at 6208.84,6132 h60
  text "Dielectric 4" at 6618.76,6132 h60
  text "370HR" at 8028.34,6132 h60
  text "8.00mil" at 8888.11,6132 h60
  text "4.2" at 9537.95,6132 h60
  text "11" at 6208.84,6012 h60
  text "Layer 5 - GND" at 6618.76,6012 h60
  text "Copper" at 8028.34,6012 h60
  text "1.42mil" at 8888.11,6012 h60
  text "12" at 6208.84,5892 h60
  text "Dielectric 5" at 6618.76,5892 h60
  text "370HR" at 8028.34,5892 h60
  text "12.60mil" at 8888.11,5892 h60
  text "4.2" at 9537.95,5892 h60
  text "13" at 6208.84,5772 h60
  text "Layer 6 - Bottom Layer" at 6618.76,5772 h60
  text "Copper" at 8028.34,5772 h60
  text "1.40mil" at 8888.11,5772 h60
  text "14" at 6208.84,5652 h60
  text "Bottom Solder" at 6618.76,5652 h60
  text "Solder Resist" at 8028.34,5652 h60
  text "0.40mil" at 8888.11,5652 h60
  text "3.5" at 9537.95,5652 h60
  text "15" at 6208.84,5532 h60
  text "Bottom Overlay" at 6618.76,5532 h60
  text ".Layer_Name" at 577,-858.49 h60
M13 Component Bodies Top:
  text ".Layer_Name" at 577,-858.49 h60
M14 Component Bodies Bottom:
  lines w10: 187.6,1022.13 862.6,1022.13 862.6,1698.13 187.6,1698.13 187.6,1022.13
  text ".Layer_Name" at 577,-858.49 h60
M15 Courtyards Top:
  text ".Layer_Name" at 577,-858.49 h60
M16 Courtyards Bottom:
  text ".Layer_Name" at 577,-858.49 h60
Drill Drawing:
  circle w10: c5363.72,2769 r27.63
  lines w10: 5336.09,2423.67 5391.34,2423.67 5363.72,2368.42 5336.09,2423.67 ; 5336.09,2492.74 5391.34,2492.74 5391.34,2547.99 5336.09,2547.99 5336.09,2492.74 ; 5336.09,2644.68 5363.72,2617.06 5391.34,2644.68 5363.72,2672.31 5336.09,2644.68 ; 5336.09,2879.51 5349.9,2879.51 5363.72,2865.7 5377.53,2879.51 5391.34,2879.51 5377.53,2893.32 5391.34,2907.14 5377.53,2907.14 5363.72,2920.95 5349.9,2907.14 5336.09,2907.14 5349.9,2893.32 5336.09,2879.51 ; 5336.09,3003.83 5349.9,3003.83 5349.9,2990.02 5377.53,2990.02 5377.53,3003.83 5391.34,3003.83 5391.34,3031.46 5377.53,3031.46 5377.53,3045.27 5349.9,3045.27 5349.9,3031.46 5336.09,3031.46 5336.09,3003.83 ; 5336.09,3114.34 5336.09,3128.15 5349.9,3141.96 5336.09,3155.78 5336.09,3169.59 5349.9,3169.59 5363.72,3155.78 5377.53,3169.59 5391.34,3169.59 5391.34,3155.78 5377.53,3141.96 5391.34,3128.15 5391.34,3114.34 5377.53,3114.34 5363.72,3128.15 5349.9,3114.34 5336.09,3114.34 ; 5336.09,3238.66 5363.72,3252.47 5391.34,3238.66 5377.53,3266.28 5391.34,3293.91 5363.72,3280.1 5336.09,3293.91 5349.9,3266.28 5336.09,3238.66
  lines w12: 5286,2331.12 8986.13,2331.12 ; 5286,3325.68 8986.13,3325.68 ; 5623.86,2206.8 5623.86,3450 ; 5955.86,2206.8 5955.86,3450 ; 6592.43,2206.8 6592.43,3450 ; 6851.57,2206.8 6851.57,3450 ; 7226.72,2206.8 7226.72,3450 ; 8419.7,2206.8 8419.7,3450 ; 5286,2206.8 8986.13,2206.8 8986.13,3450 5286,3450 5286,2206.8
  text "Symbol" at 5360.59,3362.98 h72
  text "Quantity" at 5661.16,3362.98 h72
  text "Finished Hole Size" at 5993.16,3362.98 h72
  text "Plated" at 6629.72,3362.98 h72
  text "Hole Type" at 6888.86,3362.98 h72
  text "Drill Layer Pair" at 7264.02,3362.98 h72
  text "Hole Tolerance" at 8456.99,3362.98 h72
  text "2" at 5661.16,3238.66 h60
  text "62.99mil (1.600mm)" at 5993.16,3238.66 h60
  text "NPTH" at 6629.72,3238.66 h60
  text "Round" at 6888.86,3238.66 h60
  text "Layer 1 - Top Layer - Layer 6 - Bottom Layer" at 7264.02,3238.66 h60
  text "1" at 5661.16,3114.34 h60
  text "280.00mil (7.112mm)" at 5993.16,3114.34 h60
  text "NPTH" at 6629.72,3114.34 h60
  text "Round" at 6888.86,3114.34 h60
  text "Layer 1 - Top Layer - Layer 6 - Bottom Layer" at 7264.02,3114.34 h60
  text "103" at 5661.16,2990.02 h60
  text "6.00mil (0.152mm)" at 5993.16,2990.02 h60
  text "PTH" at 6629.72,2990.02 h60
  text "Round" at 6888.86,2990.02 h60
  text "Layer 1 - Top Layer - Layer 6 - Bottom Layer" at 7264.02,2990.02 h60
  text "11" at 5661.16,2865.7 h60
  text "7.87mil (0.200mm)" at 5993.16,2865.7 h60
  text "PTH" at 6629.72,2865.7 h60
  text "Round" at 6888.86,2865.7 h60
  text "Layer 1 - Top Layer - Layer 6 - Bottom Layer" at 7264.02,2865.7 h60
  text "6" at 5661.16,2741.38 h60
  text "8.00mil (0.203mm)" at 5993.16,2741.38 h60
  text "PTH" at 6629.72,2741.38 h60
  text "Round" at 6888.86,2741.38 h60
  text "Layer 1 - Top Layer - Layer 6 - Bottom Layer" at 7264.02,2741.38 h60
  text "4" at 5661.16,2617.06 h60
  text "10.00mil (0.254mm)" at 5993.16,2617.06 h60
  text "PTH" at 6629.72,2617.06 h60
  text "Round" at 6888.86,2617.06 h60
  text "Layer 1 - Top Layer - Layer 6 - Bottom Layer" at 7264.02,2617.06 h60
  text "1" at 5661.16,2492.74 h60
  text "41.34mil (1.050mm)" at 5993.16,2492.74 h60
  text "PTH" at 6629.72,2492.74 h60
  text "Round" at 6888.86,2492.74 h60
  text "Layer 1 - Top Layer - Layer 6 - Bottom Layer" at 7264.02,2492.74 h60
  text "4" at 5661.16,2368.42 h60
  text "61.02mil (1.550mm)" at 5993.16,2368.42 h60
  text "PTH" at 6629.72,2368.42 h60
  text "Round" at 6888.86,2368.42 h60
  text "Layer 1 - Top Layer - Layer 6 - Bottom Layer" at 7264.02,2368.42 h60
  text "132 Total" at 5661.16,2244.1 h60
  text ".Layer_Name" at 577,-858.49 h60
M17 Embedded Cavity:
  text ".Layer_Name" at 577,-858.49 h60
M18 Embedded Assembly:
  text ".Layer_Name" at 577,-858.49 h60
M19 Embedded Keepout:
  text ".Layer_Name" at 577,-858.49 h60

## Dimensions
129.31,1265.01 to 924.59,1265.01 on M2 Board Dimensions
-0.61,1359.5 to 1054.51,1359.5 on M2 Board Dimensions
924.59,961.86 to 924.59,1757.14 on M2 Board Dimensions
41.95,1879.5 to 129.31,961.86 on M2 Board Dimensions
-113.05,1879.5 to 272.2,0 on M2 Board Dimensions
0,-400 to 1000,-400 on M2 Board Dimensions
